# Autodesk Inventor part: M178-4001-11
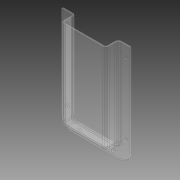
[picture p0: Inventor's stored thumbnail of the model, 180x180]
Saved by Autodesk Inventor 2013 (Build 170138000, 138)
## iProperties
Created: 2004-11
Part Number: M178-4001-11
Material: Plastic, Clear
Document SubType Name: Modeling
Designer: Autodesk, Inc.
Manufacturer: Standard
Standards Organization: Custom
Description: TOOL CADDY, PLASTIC, 4.5 x 6 x 2.5
Mass: 26.1813 g
Surface Area: 237.698 cm^2
Volume: 21.8178 cm^3
Density: 1.2 g/cm^3
CAGE: 1LJX3
Dept. ID: Product Design
Description #2: ---
Finish #1: ---
Finish #2: ---
Material ID: ---
Project Number: ---
Author: Autodesk, Inc.
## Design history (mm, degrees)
derived "M178-4001-XX.ipt"
body "Solid1"
tag "TaggingFeature2"
feature "Solid1::M178-4001-XX.ipt" dims "ScaleForDerivedMember" = 10
